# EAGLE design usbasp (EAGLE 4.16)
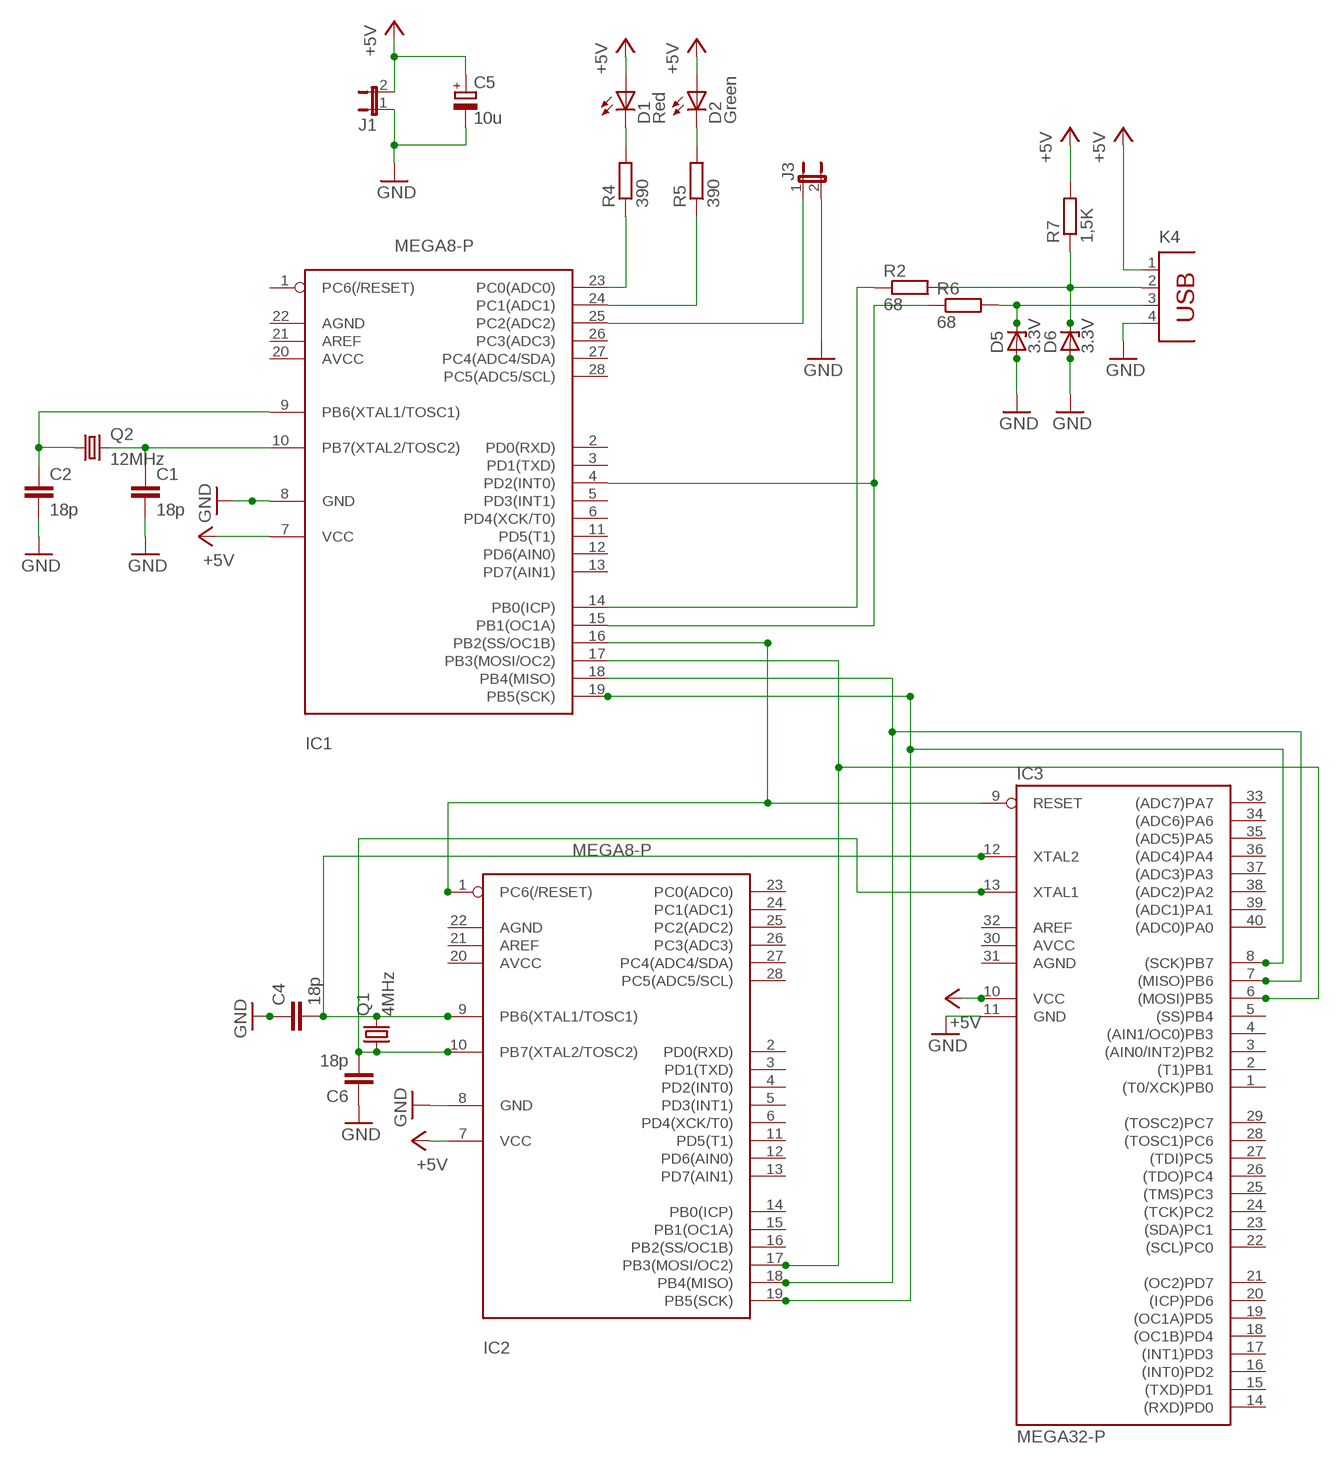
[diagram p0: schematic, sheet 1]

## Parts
C1  18p  C-EU050-025X075  [C050-025X075]
C2  18p  C-EU050-025X075  [C050-025X075]
C4  18p  C-EU050-025X075  [C050-025X075]
C5  10u  CPOL-EUE2.5-5  [E2,5-5]
C6  18p  C-EU050-025X075  [C050-025X075]
D1  Red  LED5MM  [LED5MM]
D2  Green  LED5MM  [LED5MM]
D5  3.3V  ZENER-DIODEZD-7.5  [ZDIO-7.5]
D6  3.3V  ZENER-DIODEZD-7.5  [ZDIO-7.5]
IC1  MEGA8-P  [DIL28-3]
IC2  MEGA8-P  [DIL28-3]
IC3  MEGA32-P  [DIL40]
J1  JP1E  [JP1]
J3  JP1E  [JP1]
K4  PN61729  [PN61729]
Q1  4MHz  CRYTALHC49S  [HC49/S]
Q2  12MHz  CRYTALHC49S  [HC49/S]
R2  68  R-EU_0207/10  [0207/10]
R4  390  R-EU_0207/10  [0207/10]
R5  390  R-EU_0207/10  [0207/10]
R6  68  R-EU_0207/10  [0207/10]
R7  1,5K  R-EU_0207/10  [0207/10]

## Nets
+5V: C5.+ D1.A D2.A IC1.7(VCC) IC2.7(VCC) IC3.10(VCC) J1.2 K4.1 R7.2
GND: D5.A D6.A
N$1: D6.C K4.2 R2.2 R7.1
N$2: D5.C K4.3 R6.2
N$3: C1.1 IC1.10(PB7(XTAL2/TOSC2)) Q2.2
N$4: C2.1 IC1.9(PB6(XTAL1/TOSC1)) Q2.1
N$6: IC1.18(PB4(MISO)) IC2.18(PB4(MISO)) IC3.7((MISO)PB6)
N$7: IC1.17(PB3(MOSI/OC2)) IC2.17(PB3(MOSI/OC2)) IC3.6((MOSI)PB5)
N$10: IC1.19(PB5(SCK)) IC2.19(PB5(SCK)) IC3.8((SCK)PB7)
N$12: IC1.16(PB2(SS/OC1B)) IC2.1(PC6(/RESET)) IC3.9(RESET)
N$14: IC1.14(PB0(ICP)) R2.1
N$15: IC1.25(PC2(ADC2)) J3.1
N$16: IC1.23(PC0(ADC0)) R4.1
N$17: IC1.24(PC1(ADC1)) R5.1
N$18: IC1.4(PD2(INT0)) IC1.15(PB1(OC1A)) R6.1
N$19: D1.K(C) R4.2
N$20: D2.K(C) R5.2
N$21: C4.2 IC2.9(PB6(XTAL1/TOSC1)) IC3.12(XTAL2) Q1.2
N$22: C6.2 IC2.10(PB7(XTAL2/TOSC2)) IC3.13(XTAL1) Q1.1
N$27: C1.2 C2.2 C4.1 C5.- C6.1 IC1.8(GND) IC2.8(GND) IC3.11(GND) J1.1 J3.2 K4.4 ; supply symbol labelled GND
Unconnected: IC1.1(PC6(/RESET)) IC1.2(PD0(RXD)) IC1.3(PD1(TXD)) IC1.5(PD3(INT1)) IC1.6(PD4(XCK/T0)) IC1.11(PD5(T1)) IC1.12(PD6(AIN0)) IC1.13(PD7(AIN1)) IC1.20(AVCC) IC1.21(AREF) IC1.22(AGND) IC1.26(PC3(ADC3)) IC1.27(PC4(ADC4/SDA)) IC1.28(PC5(ADC5/SCL)) IC2.2(PD0(RXD)) IC2.3(PD1(TXD)) IC2.4(PD2(INT0)) IC2.5(PD3(INT1)) IC2.6(PD4(XCK/T0)) IC2.11(PD5(T1)) IC2.12(PD6(AIN0)) IC2.13(PD7(AIN1)) IC2.14(PB0(ICP)) IC2.15(PB1(OC1A)) IC2.16(PB2(SS/OC1B)) IC2.20(AVCC) IC2.21(AREF) IC2.22(AGND) IC2.23(PC0(ADC0)) IC2.24(PC1(ADC1)) IC2.25(PC2(ADC2)) IC2.26(PC3(ADC3)) IC2.27(PC4(ADC4/SDA)) IC2.28(PC5(ADC5/SCL)) IC3.1((T0/XCK)PB0) IC3.2((T1)PB1) IC3.3((AIN0/INT2)PB2) IC3.4((AIN1/OC0)PB3) IC3.5((SS)PB4) IC3.14((RXD)PD0) IC3.15((TXD)PD1) IC3.16((INT0)PD2) IC3.17((INT1)PD3) IC3.18((OC1B)PD4) IC3.19((OC1A)PD5) IC3.20((ICP)PD6) IC3.21((OC2)PD7) IC3.22((SCL)PC0) IC3.23((SDA)PC1) IC3.24((TCK)PC2) IC3.25((TMS)PC3) IC3.26((TDO)PC4) IC3.27((TDI)PC5) IC3.28((TOSC1)PC6) IC3.29((TOSC2)PC7) IC3.33((ADC7)PA7) IC3.34((ADC6)PA6) IC3.35((ADC5)PA5) IC3.36((ADC4)PA4) IC3.37((ADC3)PA3) IC3.38((ADC2)PA2) IC3.39((ADC1)PA1) IC3.40((ADC0)PA0)

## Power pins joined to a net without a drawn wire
AGND: IC3.31(AGND)
AREF: IC3.32(AREF)
AVCC: IC3.30(AVCC)

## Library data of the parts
C1 C2 C4 C6 = rcl:C-EU: CAPACITOR, European symbol
C5 = rcl:CPOL-EU: POLARIZED CAPACITOR, European symbol
D1 D2 = led:LED: LED
D5 D6 = diode:ZENER-DIODE: Z-Diode
IC1 IC2 = atmel:MEGA8-P: MICROCONTROLLER 8 Kbytes FLASH 1 kbytes SRAM 512 bytes EEPROM USART 4-channel 10 bit ADC 2-channel 8 bit ADC Source: avr.lbr
IC3 = atmel:MEGA32-P: MICROCONTROLLER 32 Kbytes FLASH 2 Kbytes SRAM 1 Kbytes EEPROM USART 8-channel 10 bit ADC Source: www.atmel.com .. doc2503.pdf
J1 J3 = jumper:JP1E: JUMPER
K4 = con-berg:PN61729: BERG USB connector
Q1 Q2 = crystal:CRYTAL: CRYSTAL
R2 R4-R7 = rcl:R-EU_: RESISTOR, European symbol

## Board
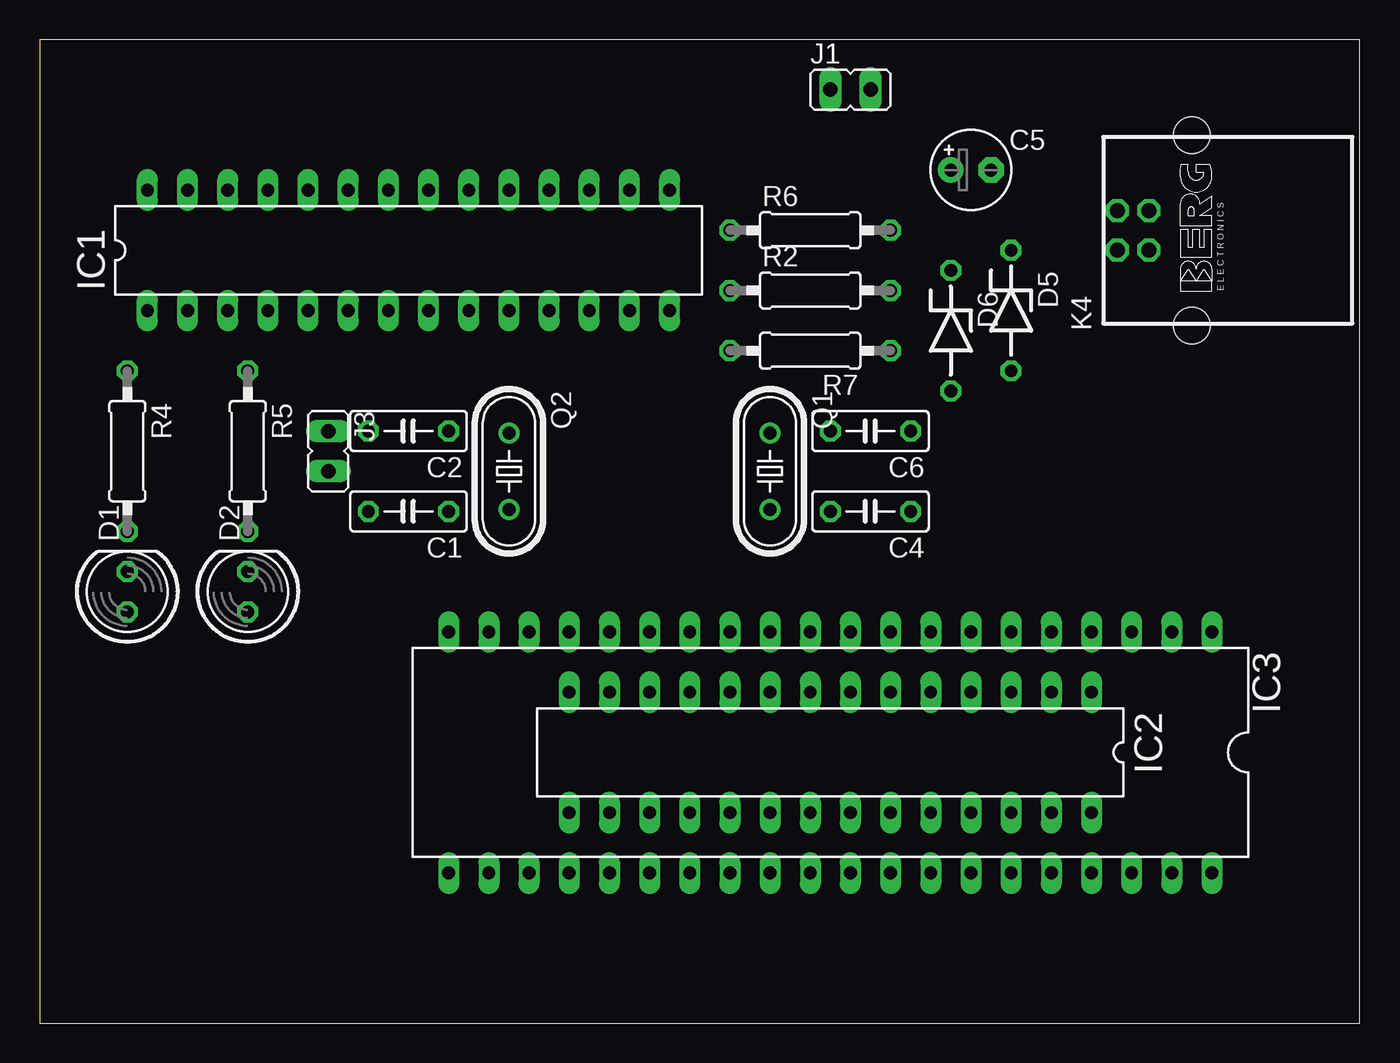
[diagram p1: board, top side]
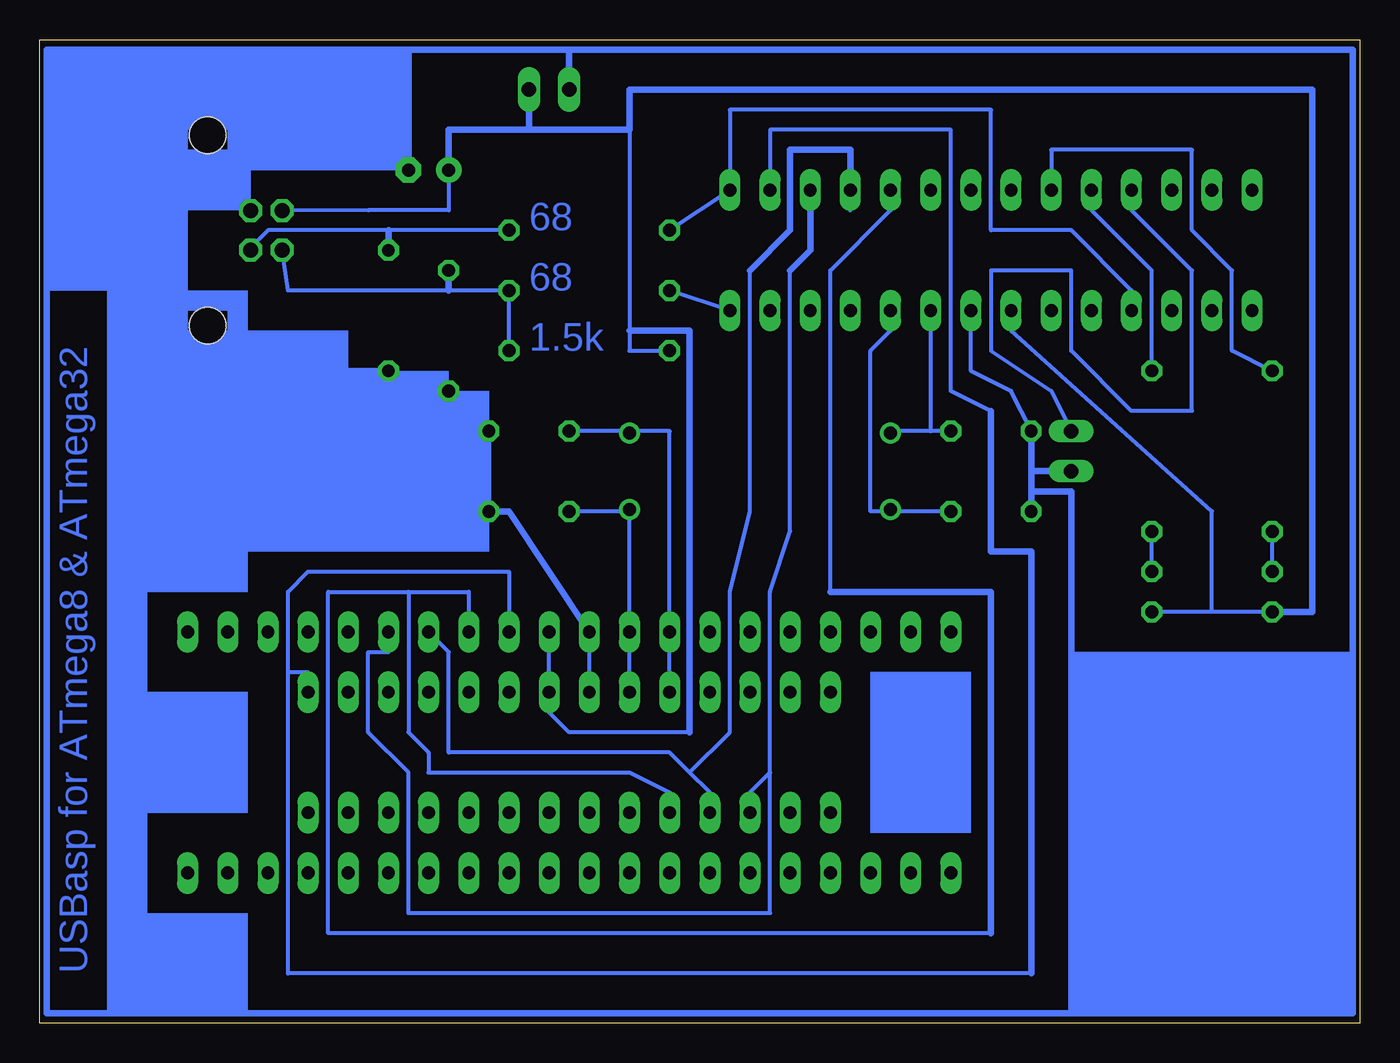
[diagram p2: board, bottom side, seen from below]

Size 83.49 x 62.22 mm. Coordinates in mm from the lower left corner, seen from the top.
Outline: 0,0 83.49,0 83.49,62.22 0,62.22 0,0
Copper layers 16: Bottom 0.035mm
Design rules "default": minimum track width 10mil, minimum drill 24mil, track to track 30mil, track to pad 8mil, pad to pad 8mil, via to via 8mil, smd to smd 8mil, copper to edge 40mil, drill to drill 8mil, minimum pad ring 10mil, minimum via ring 8mil, stop-mask expansion 4mil, vias tented up to drill 0mil, thermal gap 10mil

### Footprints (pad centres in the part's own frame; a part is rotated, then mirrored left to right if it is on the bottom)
C050-025X075 = drill 0.813 octagon: 1 -2.54,0; 2 2.54,0
E2,5-5 = drill 0.813 pad 1.6 round: + -1.27,0 | drill 0.813 pad 1.6 octagon: - 1.27,0
LED5MM = drill 0.813 octagon: A -1.27,0; K 1.27,0
ZDIO-7.5 = drill 0.813 octagon: A 3.81,0; C -3.81,0
DIL28-3 = drill 0.813 long: 1 -16.51,-3.81; 2 -13.97,-3.81; 3 -11.43,-3.81; 4 -8.89,-3.81; 5 -6.35,-3.81; 6 -3.81,-3.81; 7 -1.27,-3.81; 8 1.27,-3.81; 9 3.81,-3.81; 10 6.35,-3.81; 11 8.89,-3.81; 12 11.43,-3.81; 13 13.97,-3.81; 14 16.51,-3.81; 15 16.51,3.81; 16 13.97,3.81; 17 11.43,3.81; 18 8.89,3.81; 19 6.35,3.81; 20 3.81,3.81; 21 1.27,3.81; 22 -1.27,3.81; 23 -3.81,3.81; 24 -6.35,3.81; 25 -8.89,3.81; 26 -11.43,3.81; 27 -13.97,3.81; 28 -16.51,3.81
DIL40 = drill 0.813 long: 1 -24.13,-7.62; 2 -21.59,-7.62; 3 -19.05,-7.62; 4 -16.51,-7.62; 5 -13.97,-7.62; 6 -11.43,-7.62; 7 -8.89,-7.62; 8 -6.35,-7.62; 9 -3.81,-7.62; 10 -1.27,-7.62; 11 1.27,-7.62; 12 3.81,-7.62; 13 6.35,-7.62; 14 8.89,-7.62; 15 11.43,-7.62; 16 13.97,-7.62; 17 16.51,-7.62; 18 19.05,-7.62; 19 21.59,-7.62; 20 24.13,-7.62; 21 24.13,7.62; 22 21.59,7.62; 23 19.05,7.62; 24 16.51,7.62; 25 13.97,7.62; 26 11.43,7.62; 27 8.89,7.62; 28 6.35,7.62; 29 3.81,7.62; 30 1.27,7.62; 31 -1.27,7.62; 32 -3.81,7.62; 33 -6.35,7.62; 34 -8.89,7.62; 35 -11.43,7.62; 36 -13.97,7.62; 37 -16.51,7.62; 38 -19.05,7.62; 39 -21.59,7.62; 40 -24.13,7.62
JP1 = drill 0.914 long: 1 0,-1.27; 2 0,1.27
PN61729 = drill 0.95 octagon: 1 1.25,4.71; 2 -1.25,4.71; 3 -1.25,2.71; 4 1.25,2.71 | hole 2.3: -6.02,0; 6.02,0
HC49/S = drill 0.813 round: 1 -2.413,0; 2 2.413,0
0207/10 = drill 0.813 octagon: 1 -5.08,0; 2 5.08,0

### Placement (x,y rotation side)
C1  23.33,32.38 180 top
C2  23.33,37.46 180 top
C4  52.54,32.38 180 top
C5  58.89,53.97 0 top
C6  52.54,37.46 180 top
D1  5.55,27.3 90 top
D2  13.17,27.3 90 top
D5  61.43,45.08 270 top
D6  57.62,43.81 270 top
IC1  23.33,48.89 0 top
IC2  50,17.14 180 top
IC3  50,17.14 180 top
J1  51.27,59.05 270 top
J3  18.25,36.19 180 top
K4  72.86,50.16 90 top
Q1  46.19,34.92 270 top
Q2  29.68,34.92 270 top
R2  48.73,46.35 0 top
R4  5.55,36.19 270 top
R5  13.17,36.19 270 top
R6  48.73,50.16 0 top
R7  48.73,42.54 180 top

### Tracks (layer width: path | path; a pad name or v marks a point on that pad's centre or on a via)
+5V
  Bottom 0.254: D1.A 9.36,26.03 | 9.36,26.03 9.36,32.38 22.06,43.81 IC1.7 | IC3.10 IC2.7 51.27,19.68 50,18.41 42.38,18.41 | R7.2 46.19,42.54 46.19,43.81 46.19,56.51 | C5.+ 57.62,51.43 62.7,51.43 K4.1 | 9.36,26.03 D2.A
  Bottom 0.406: C5.+ 57.62,56.51 52.54,56.51 | 52.54,56.51 46.19,56.51 46.19,59.05 3.01,59.05 3.01,26.03 D1.A | 42.38,18.41 42.38,43.81 46.19,43.81 | 52.54,56.51 J1.2
GND
  Bottom 0.406: D6.A 61.43,40 D5.A
N$1
  Bottom 0.254: R7.1 R2.2 57.62,46.35 67.78,46.35 K4.2
  Bottom 0.406: 57.62,46.35 D6.C
N$2
  Bottom 0.254: R6.2 61.43,50.16 69.05,50.16 70.32,48.89 K4.3
  Bottom 0.406: 61.43,50.16 D5.C
N$3
  Bottom 0.254: C1.1 29.68,32.38 | 29.68,32.38 30.95,32.38 30.95,42.54 29.68,43.81 IC1.10 | 29.68,32.38 Q2.2
N$4
  Bottom 0.254: 27.14,37.46 29.68,37.46 Q2.1 | C2.1 27.14,37.46 | 27.14,37.46 IC1.9
N$6
  Bottom 0.254: IC1.18 32.22,51.43 | 42.38,15.87 43.65,17.14 57.62,17.14 57.62,23.49 IC3.7 | 42.38,15.87 41.11,14.6 IC2.18 | 38.57,47.62 38.57,32.38 39.84,27.3 39.84,18.41 42.38,15.87
  Bottom 0.406: 38.57,47.62 36.03,50.16 36.03,55.24 32.22,55.24 IC1.18
N$7
  Bottom 0.254: 36.03,47.62 36.03,31.11 37.3,27.3 37.3,15.87 | 37.3,15.87 38.57,14.6 IC2.17 | 37.3,15.87 37.3,6.98 60.16,6.98 60.16,15.87 62.7,18.41 62.7,23.49 61.43,23.49 IC3.6 | 34.76,51.43 IC1.17
  Bottom 0.406: 34.76,51.43 34.76,48.89 36.03,47.62
N$10
  Bottom 0.254: 60.16,27.3 60.16,18.41 58.89,17.14 58.89,15.87 46.19,15.87 43.65,14.6 IC2.19 | 60.16,27.3 56.35,27.3 IC3.8 | 33.49,27.3 33.49,47.62 29.68,51.43 IC1.19 | 23.33,5.71 65.24,5.71 65.24,27.3 60.16,27.3
  Bottom 0.406: 33.49,27.3 23.33,27.3 23.33,5.71
N$12
  Bottom 0.254: 67.78,22.22 66.51,22.22 IC2.1 | 67.78,22.22 67.78,27.3 66.51,28.57 53.81,28.57 IC3.9 | 23.33,38.73 25.87,40 25.87,56.51 37.3,56.51 IC1.16 | 20.79,3.17 67.78,3.17 67.78,22.22
  Bottom 0.406: 23.33,38.73 23.33,29.84 20.79,29.84 20.79,3.17
N$14
  Bottom 0.254: IC1.14 R2.1
N$15
  Bottom 0.254: J3.1 19.52,40 23.33,42.54 23.33,47.62 18.25,47.62 18.25,42.54 14.44,38.73 10.63,38.73 10.63,47.62 14.44,51.43 IC1.25
N$16
  Bottom 0.254: R4.1 8.09,42.54 8.09,47.62 10.63,50.16 10.63,55.24 19.52,55.24 IC1.23
N$17
  Bottom 0.254: R5.1 13.17,47.62 16.98,51.43 IC1.24
N$18
  Bottom 0.254: IC1.4 14.44,46.35 18.25,50.16 23.33,50.16 23.33,57.78 39.84,57.78 IC1.15 R6.1
N$19
  Bottom 0.254: D1.K R4.2
N$20
  Bottom 0.254: D2.K R5.2
N$21
  Bottom 0.254: IC2.9 IC3.12 46.19,32.38 | 46.19,32.38 C4.2 | 46.19,32.38 Q1.2
N$22
  Bottom 0.254: IC2.10 IC3.13 43.65,37.46 46.19,37.46 | 46.19,37.46 C6.2 | 46.19,37.46 Q1.1
N$27
  Bottom 0.254: C2.2 22.06,40 24.6,41.27 IC1.8 | IC3.11 IC2.8 | C6.1 C4.1
  Bottom 0.406: K4.4 70.3,51.41 70.32,51.43 70.32,61.59 | 50,61.59 0.47,61.59 0.47,0.63 18.25,0.63 | 60.16,61.59 50,61.59 | 60.16,61.59 C5.- | IC3.11 53.81,32.38 C4.1 | C6.1 57.62,37.46 57.62,40 61.43,40 61.43,41.27 76.67,41.27 76.67,61.59 | 70.32,61.59 60.16,61.59 | 50,61.59 J1.1 | 20.79,34.92 J3.2 | 20.79,34.92 C2.2 | 20.79,33.65 20.79,34.92 | 20.79,33.65 C1.2 | 20.79,33.65 18.25,33.65 18.25,0.63 | 18.25,0.63 83.02,0.63 83.02,61.59 76.67,61.59 | 70.32,61.59 76.67,61.59
(copper drawn outside any net)
  shapes: Bottom area x20

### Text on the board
Bottom: 68 | 68 | 1.5k | USBasp for ATmega8 & ATmega32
